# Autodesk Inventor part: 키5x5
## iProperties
Company: 한국ATC센터
Created: 2014-12
Part Number: 키5x5
Document SubType Name: Modeling
Designer: KYOUNG IL JANG
Density: 1 g/cm^3
Mass: 0.323175 g
Surface Area: 2.9781 cm^2
Volume: 0.323175 cm^3
Author: KYOUNG IL JANG
